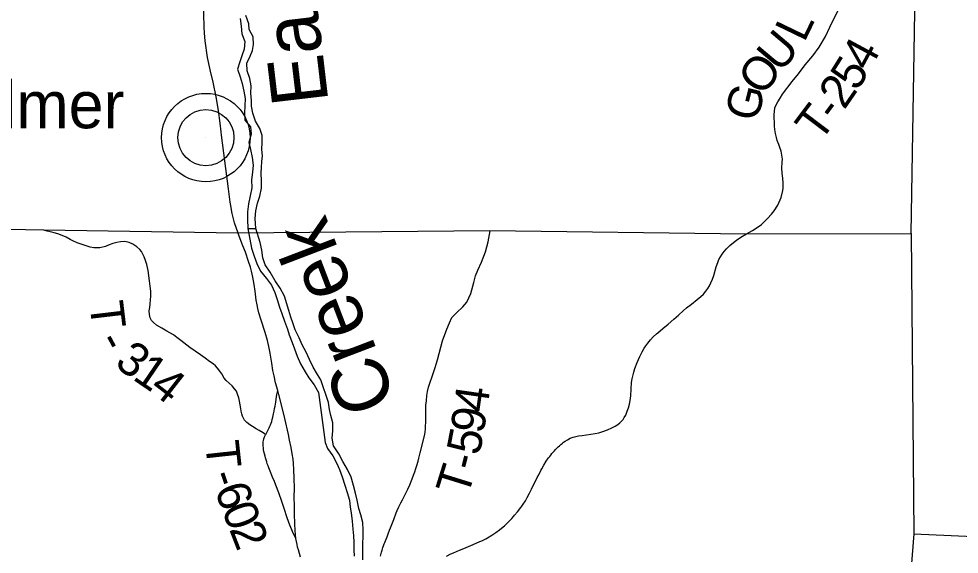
# Model space of a CAD drawing. Extents: x -10.5 to 40.6, y -3.2 to 22.
# Drawn here: x -7.693 to -6.111, y 16.857 to 17.758 of the extents above; entities that cross this region are included whole.
import ezdxf

# ---------------------------------------------------------------- set-up
doc = ezdxf.new("R2010")
doc.units = 0
for name, color, linetype in [('GM_X_Major_River', 7, 'Continuous'), ('GM_X_Major_River_Text', 7, 'Continuous'), ('GM_X_State_Route', 7, 'Continuous'), ('GM_X_Township_Road', 7, 'Continuous'), ('GM_X_Township_Road_Text', 7, 'Continuous'), ('GM_X_Township_Text', 7, 'Continuous'), ('GM_X_Unincorporated', 7, 'Continuous'), ('GM_X_Unincorporated_Location', 7, 'Continuous'), ('GM_X_Unincorporated_Text', 7, 'Continuous')]:
    doc.layers.add(name, color=color, linetype=linetype)

msp = doc.modelspace()

# ---------------------------------------------------------------- linework, layer by layer
at = {"layer": 'GM_X_Major_River'}
msp.add_line((-7.3076, 17.4047), (-7.2943, 17.4046), dxfattribs=at)
for points in [[(-7.2943, 17.4046), (-7.2951, 17.4214), (-7.2938, 17.4343), (-7.291, 17.4472), (-7.2875, 17.4594), (-7.2847, 17.4728), (-7.2846, 17.4853), (-7.2852, 17.4982), (-7.2843, 17.5077), (-7.2837, 17.5175), (-7.2827, 17.527), (-7.2841, 17.538), (-7.2832, 17.5494), (-7.2834, 17.5612), (-7.2874, 17.5732), (-7.2945, 17.5852), (-7.2993, 17.5988), (-7.3011, 17.6105), (-7.3013, 17.6204), (-7.3022, 17.6325), (-7.3017, 17.6446), (-7.3039, 17.6571), (-7.3087, 17.6703), (-7.3089, 17.6832), (-7.3038, 17.6946), (-7.2999, 17.7042), (-7.2982, 17.7141), (-7.2984, 17.727), (-7.3055, 17.7394), (-7.306, 17.7492), (-7.3109, 17.7632)], [(-7.3206, 17.758), (-7.3189, 17.7452), (-7.3178, 17.7323), (-7.3123, 17.7195), (-7.3139, 17.7066), (-7.3172, 17.697), (-7.3211, 17.6852), (-7.3247, 17.673), (-7.3202, 17.6602), (-7.317, 17.6489), (-7.3141, 17.636), (-7.3119, 17.6236), (-7.3125, 17.6114), (-7.3133, 17.5989), (-7.3127, 17.5871), (-7.303, 17.5756), (-7.302, 17.5635), (-7.3056, 17.5497), (-7.303, 17.5376), (-7.3001, 17.5244), (-7.2984, 17.5116), (-7.2996, 17.4994), (-7.3013, 17.4868), (-7.3007, 17.4732), (-7.3034, 17.4599), (-7.3062, 17.4462), (-7.3078, 17.4329), (-7.3083, 17.42), (-7.3076, 17.4047)], [(-7.3076, 17.4047), (-7.3013, 17.3718), (-7.2969, 17.3582), (-7.2926, 17.3457), (-7.2863, 17.3333), (-7.2759, 17.3205), (-7.2678, 17.3093), (-7.2623, 17.2972), (-7.258, 17.2855), (-7.254, 17.2727), (-7.2505, 17.2621), (-7.2458, 17.2492), (-7.2406, 17.2357), (-7.2379, 17.2258), (-7.2331, 17.213), (-7.2292, 17.2024), (-7.2245, 17.19), (-7.219, 17.1772), (-7.2109, 17.164), (-7.205, 17.1539), (-7.1961, 17.1418), (-7.1884, 17.129), (-7.1776, 17.0447)], [(-7.1845, 17.1501), (-7.1903, 17.1594), (-7.1977, 17.1718), (-7.2036, 17.1846), (-7.2094, 17.1966), (-7.216, 17.2091), (-7.2211, 17.2211), (-7.2281, 17.2343), (-7.2317, 17.246), (-7.2352, 17.2558), (-7.2384, 17.2668), (-7.2456, 17.291), (-7.2533, 17.3045), (-7.2615, 17.3169), (-7.27, 17.3312), (-7.2781, 17.3436), (-7.2825, 17.3553), (-7.2838, 17.3682), (-7.287, 17.3814), (-7.2943, 17.4046)], [(-7.1139, 16.8472), (-7.1141, 16.8726), (-7.1135, 16.8882), (-7.1136, 16.8981), (-7.1141, 16.9102), (-7.1172, 16.9231), (-7.1207, 16.9337), (-7.1239, 16.9477), (-7.1263, 16.9594), (-7.1298, 16.9727), (-7.1338, 16.9867), (-7.14, 16.9995), (-7.1477, 17.0131), (-7.1546, 17.026), (-7.1635, 17.0392), (-7.1659, 17.0521), (-7.1645, 17.0646), (-7.1646, 17.0779), (-7.1677, 17.09), (-7.1701, 17.1002), (-7.1721, 17.1124), (-7.1845, 17.1501)], [(-7.1776, 17.0447), (-7.1737, 17.0349), (-7.1645, 17.0225), (-7.1579, 17.0096), (-7.1536, 16.9994), (-7.1489, 16.9869), (-7.1446, 16.9733), (-7.1404, 16.9608), (-7.1364, 16.9479), (-7.1352, 16.9358), (-7.1336, 16.9263), (-7.1319, 16.9123), (-7.1307, 16.899), (-7.1298, 16.8876), (-7.1293, 16.8774), (-7.1292, 16.8641), (-7.1284, 16.8539)]]:
    msp.add_lwpolyline(points, dxfattribs=at)
at = {"layer": 'GM_X_State_Route'}
for points in [[(-7.3365, 17.4464), (-7.337, 17.4494), (-7.3399, 17.4715), (-7.3443, 17.5057), (-7.3519, 17.5616), (-7.3524, 17.5674), (-7.3541, 17.5819), (-7.3568, 17.6036), (-7.3605, 17.6264), (-7.3656, 17.6509), (-7.3703, 17.6696), (-7.3752, 17.6927), (-7.3794, 17.7205), (-7.3806, 17.7334), (-7.381, 17.7436), (-7.3823, 17.7886)], [(-7.3239, 17.3969), (-7.3298, 17.4143), (-7.3339, 17.4303), (-7.3365, 17.4464)], [(-7.2188, 16.8519), (-7.2207, 16.8583), (-7.2224, 16.8644), (-7.2237, 16.869), (-7.2247, 16.8735), (-7.2256, 16.8784), (-7.2265, 16.8831), (-7.2273, 16.8901), (-7.2279, 16.8969), (-7.2285, 16.908), (-7.2287, 16.9124), (-7.2289, 16.9204), (-7.229, 16.9272), (-7.2292, 16.9365), (-7.2292, 16.9427), (-7.2293, 16.9483), (-7.2294, 16.9526), (-7.2292, 16.9688), (-7.2294, 16.9843), (-7.2299, 16.9992), (-7.2307, 17.0097), (-7.2315, 17.017), (-7.2327, 17.0256), (-7.2347, 17.0366), (-7.2372, 17.0487), (-7.2392, 17.0584), (-7.2452, 17.0851), (-7.2503, 17.1062), (-7.2554, 17.1254), (-7.2573, 17.1324), (-7.2608, 17.1452), (-7.2634, 17.1568), (-7.2652, 17.1659), (-7.2672, 17.1782), (-7.2699, 17.1954), (-7.272, 17.2063), (-7.2745, 17.2166), (-7.2782, 17.2297), (-7.2852, 17.2509), (-7.2888, 17.2628), (-7.2906, 17.2701), (-7.2919, 17.2762), (-7.2932, 17.2842), (-7.2951, 17.2996), (-7.2968, 17.3107), (-7.2991, 17.3228), (-7.3013, 17.3331), (-7.3031, 17.3396), (-7.3063, 17.3496), (-7.3116, 17.3648), (-7.3158, 17.3757), (-7.3221, 17.3919), (-7.3239, 17.3969)]]:
    msp.add_lwpolyline(points, dxfattribs=at)
at = {"layer": 'GM_X_Township_Road'}
for points in [[(-6.469, 17.3956), (-6.4587, 17.4013), (-6.4491, 17.4075), (-6.4436, 17.4117), (-6.4385, 17.4166), (-6.4334, 17.4217), (-6.427, 17.429), (-6.4222, 17.4348), (-6.4161, 17.4439), (-6.4107, 17.4568), (-6.408, 17.4685), (-6.4075, 17.4726), (-6.4071, 17.4813), (-6.4078, 17.4893), (-6.4091, 17.4979), (-6.4094, 17.5064), (-6.409, 17.5164), (-6.4086, 17.5213), (-6.4094, 17.528), (-6.4107, 17.5349), (-6.4127, 17.5409), (-6.4148, 17.546), (-6.4172, 17.5526), (-6.4186, 17.558), (-6.42, 17.5644), (-6.421, 17.5711), (-6.4216, 17.5769), (-6.4221, 17.5829), (-6.4224, 17.5908), (-6.4225, 17.5964), (-6.422, 17.6018), (-6.421, 17.6076), (-6.4191, 17.6128), (-6.4164, 17.6181), (-6.4124, 17.6242), (-6.4082, 17.6308), (-6.3919, 17.6519), (-6.3817, 17.6653), (-6.37, 17.6804), (-6.3576, 17.6955), (-6.3469, 17.7101), (-6.3359, 17.7279), (-6.3285, 17.7433), (-6.3082, 17.7853)], [(-7.2772, 17.0584), (-7.2792, 17.0596), (-7.2815, 17.0609), (-7.2883, 17.0652), (-7.2933, 17.0681), (-7.2999, 17.0715), (-7.3041, 17.0744), (-7.3093, 17.0784), (-7.313, 17.0823), (-7.3164, 17.0889), (-7.3173, 17.0932), (-7.3187, 17.0977), (-7.3193, 17.1023), (-7.3215, 17.1145), (-7.3228, 17.12), (-7.3246, 17.1259), (-7.3268, 17.1313), (-7.3299, 17.1353), (-7.3337, 17.1404), (-7.3437, 17.1491), (-7.347, 17.1531), (-7.3511, 17.1602), (-7.3543, 17.1648), (-7.3583, 17.1701), (-7.3617, 17.1736), (-7.366, 17.1772), (-7.3718, 17.1813), (-7.3794, 17.1865), (-7.3873, 17.1924), (-7.3963, 17.1986), (-7.4049, 17.2048), (-7.4201, 17.2165), (-7.4271, 17.2213), (-7.4325, 17.226), (-7.4437, 17.2322), (-7.4523, 17.2371), (-7.4609, 17.2423), (-7.4662, 17.2469), (-7.4695, 17.25), (-7.4718, 17.2543), (-7.4729, 17.2604), (-7.4732, 17.2662), (-7.4722, 17.2718), (-7.4706, 17.291), (-7.4706, 17.2994), (-7.4717, 17.3078), (-7.4731, 17.3169), (-7.4753, 17.3341), (-7.4773, 17.3443), (-7.4793, 17.3511), (-7.4816, 17.357), (-7.4839, 17.3616), (-7.4862, 17.3659), (-7.4892, 17.3694), (-7.4944, 17.3741), (-7.5009, 17.3785), (-7.507, 17.3812), (-7.5143, 17.3828), (-7.5214, 17.3824), (-7.5276, 17.3813), (-7.5344, 17.3795), (-7.5407, 17.3774), (-7.5471, 17.3748), (-7.5562, 17.3726), (-7.5613, 17.3721), (-7.5667, 17.3724), (-7.5725, 17.3736), (-7.5796, 17.3759), (-7.5878, 17.3787), (-7.5943, 17.3808), (-7.6015, 17.3841), (-7.606, 17.3865), (-7.6131, 17.39), (-7.6198, 17.3931), (-7.6271, 17.3957), (-7.633, 17.3974), (-7.6399, 17.3992), (-7.6452, 17.4003), (-7.6507, 17.4021)], [(-7.0846, 16.8539), (-7.0827, 16.8604), (-7.0815, 16.8639), (-7.0802, 16.8681), (-7.0791, 16.8712), (-7.078, 16.8742), (-7.0769, 16.8769), (-7.0758, 16.8795), (-7.0748, 16.8822), (-7.0732, 16.8862), (-7.0713, 16.8914), (-7.0691, 16.8972), (-7.0675, 16.9012), (-7.062, 16.9156), (-7.0579, 16.9263), (-7.0561, 16.9307), (-7.0533, 16.9368), (-7.05, 16.9434), (-7.0476, 16.9484), (-7.0445, 16.9539), (-7.041, 16.9609), (-7.0384, 16.9664), (-7.0353, 16.9736), (-7.0312, 16.984), (-7.029, 16.9898), (-7.0268, 16.9956), (-7.0248, 17.001), (-7.0233, 17.006), (-7.021, 17.0133), (-7.0198, 17.0187), (-7.0174, 17.0272), (-7.0107, 17.0537), (-7.0098, 17.0591), (-7.0094, 17.0622), (-7.0089, 17.0677), (-7.0086, 17.0733), (-7.0084, 17.0782), (-7.0084, 17.0795), (-7.0084, 17.0819), (-7.0084, 17.0831), (-7.0083, 17.0861), (-7.0083, 17.0928), (-7.0082, 17.1002), (-7.0079, 17.1076), (-7.0073, 17.115), (-7.0064, 17.1237), (-7.0052, 17.1304), (-7.0035, 17.1377), (-7.002, 17.143), (-7.0009, 17.1466), (-6.9983, 17.1541), (-6.9959, 17.161), (-6.9924, 17.1712), (-6.9908, 17.1764), (-6.9887, 17.1841), (-6.9799, 17.2159), (-6.9731, 17.2356), (-6.9684, 17.2459), (-6.9644, 17.2549), (-6.9568, 17.2631), (-6.9462, 17.2728), (-6.9393, 17.281), (-6.9324, 17.2954), (-6.9277, 17.3141), (-6.9249, 17.3251), (-6.9208, 17.3347), (-6.9143, 17.3482), (-6.908, 17.3654), (-6.9033, 17.3826), (-6.9002, 17.401)], [(-6.9733, 16.8539), (-6.966, 16.8573), (-6.9615, 16.8593), (-6.9518, 16.8637), (-6.9444, 16.8668), (-6.9284, 16.8735), (-6.9175, 16.8782), (-6.9141, 16.8797), (-6.9108, 16.8813), (-6.9075, 16.883), (-6.9042, 16.8847), (-6.8972, 16.8887), (-6.8905, 16.8932), (-6.884, 16.8981), (-6.8779, 16.9032), (-6.876, 16.9049), (-6.871, 16.9095), (-6.8663, 16.9143), (-6.8637, 16.9169), (-6.8608, 16.9201), (-6.8588, 16.9225), (-6.854, 16.9282), (-6.8483, 16.9355), (-6.8465, 16.938), (-6.8443, 16.9411), (-6.8405, 16.9468), (-6.8375, 16.9524), (-6.8336, 16.9599), (-6.8302, 16.9666), (-6.8207, 16.9862), (-6.8184, 16.9906), (-6.8147, 16.9978), (-6.8133, 17.0005), (-6.8096, 17.0069), (-6.8056, 17.0132), (-6.8016, 17.0188), (-6.7997, 17.0212), (-6.798, 17.0238), (-6.7962, 17.0261), (-6.7937, 17.029), (-6.7919, 17.0311), (-6.79, 17.0331), (-6.7878, 17.0352), (-6.7857, 17.0374), (-6.7835, 17.0395), (-6.7812, 17.0416), (-6.7783, 17.044), (-6.7764, 17.0455), (-6.7739, 17.0473), (-6.7702, 17.0494), (-6.7652, 17.0519), (-6.7606, 17.0537), (-6.7558, 17.0551), (-6.7516, 17.056), (-6.7454, 17.0569), (-6.7306, 17.0587), (-6.7233, 17.0599), (-6.7172, 17.0613), (-6.7107, 17.0633), (-6.7025, 17.0664), (-6.6951, 17.0696), (-6.6896, 17.0725), (-6.6855, 17.0751), (-6.682, 17.0778), (-6.6789, 17.0808), (-6.6765, 17.0837), (-6.6744, 17.0867), (-6.6721, 17.0911), (-6.6694, 17.0974), (-6.6673, 17.1032), (-6.6657, 17.1092), (-6.6646, 17.1153), (-6.6636, 17.1233), (-6.6628, 17.1345), (-6.6621, 17.1456), (-6.6613, 17.1518), (-6.6603, 17.1567), (-6.6585, 17.1632), (-6.6566, 17.1691), (-6.6525, 17.1795), (-6.6481, 17.1897), (-6.6443, 17.1976), (-6.641, 17.2036), (-6.6383, 17.2077), (-6.6349, 17.2121), (-6.6305, 17.2174), (-6.6258, 17.2224), (-6.6205, 17.2276), (-6.6182, 17.2296), (-6.6096, 17.2368), (-6.6004, 17.2441), (-6.591, 17.2522), (-6.5832, 17.2593), (-6.575, 17.2669), (-6.5698, 17.2713), (-6.5614, 17.2778), (-6.5516, 17.2854), (-6.5459, 17.2902), (-6.5415, 17.2946), (-6.5374, 17.2992), (-6.5341, 17.3037), (-6.5312, 17.3085), (-6.5287, 17.3135), (-6.526, 17.3198), (-6.5241, 17.3257), (-6.5198, 17.3406), (-6.5173, 17.3476), (-6.5152, 17.3527), (-6.5128, 17.3571), (-6.5098, 17.3618), (-6.5064, 17.3663), (-6.5026, 17.3704), (-6.4968, 17.376), (-6.4907, 17.3813), (-6.4858, 17.3851), (-6.4786, 17.39), (-6.469, 17.3956)], [(-7.2772, 17.0584), (-7.2768, 17.0592), (-7.2715, 17.0697), (-7.2703, 17.0723), (-7.2693, 17.0748), (-7.2682, 17.0776), (-7.2674, 17.0801), (-7.2664, 17.0838), (-7.2655, 17.0873), (-7.2642, 17.0929), (-7.2632, 17.0975), (-7.2624, 17.1018), (-7.2616, 17.106), (-7.2606, 17.1125), (-7.2598, 17.1178), (-7.2585, 17.1255), (-7.2573, 17.1324)], [(-7.2265, 16.8831), (-7.2322, 16.8949), (-7.2335, 16.8977), (-7.2367, 16.9057), (-7.2411, 16.918), (-7.2464, 16.9338), (-7.2487, 16.9408), (-7.2514, 16.949), (-7.254, 16.9566), (-7.2552, 16.96), (-7.2603, 16.973), (-7.2629, 16.9793), (-7.2659, 16.9867), (-7.27, 16.9969), (-7.2722, 17.002), (-7.2735, 17.0055), (-7.2748, 17.0092), (-7.2757, 17.0125), (-7.2767, 17.0159), (-7.2775, 17.0188), (-7.2783, 17.0218), (-7.2795, 17.026), (-7.2804, 17.0297), (-7.281, 17.0326), (-7.2814, 17.0359), (-7.2817, 17.0395), (-7.2818, 17.0417), (-7.2817, 17.0441), (-7.2816, 17.0459), (-7.2812, 17.0483), (-7.2805, 17.0508), (-7.2793, 17.0542), (-7.2777, 17.0576), (-7.2772, 17.0584)]]:
    msp.add_lwpolyline(points, dxfattribs=at)
at = {"layer": 'GM_X_Township_Text'}
for points in [[(-6.192, 17.3965), (-6.1792, 18.1778), (-6.179, 18.1863), (-6.1678, 18.8746), (-6.1678, 18.8755), (-6.1618, 20.9), (-10.5445, 20.9), (-10.5445, 19.4241)], [(-10.5445, 19.4241), (-9.8621, 19.4152), (-9.3297, 19.4093), (-9.2736, 19.4089), (-9.2734, 18.9532), (-9.2666, 18.9242), (-9.2573, 18.7823), (-9.2552, 18.7211), (-9.2586, 18.705), (-9.2677, 18.6789), (-9.2756, 18.3974), (-9.1719, 18.3965), (-8.6421, 18.3977), (-8.2403, 18.3894), (-8.2411, 17.9704), (-8.2441, 17.4134), (-7.9861, 17.4086), (-7.6509, 17.4026), (-7.3241, 17.3974), (-6.9004, 17.4016), (-6.4692, 17.3961), (-6.192, 17.3965), (-6.1874, 16.891), (-6.062, 16.8858)], [(-6.1874, 16.891), (-6.1985, 16.7494), (-6.1956, 16.4198), (-6.1883, 16.2366), (-6.1993, 15.3843), (-6.2122, 14.1), (-3.7445, 14.1), (-3.7445, 16.8499)]]:
    msp.add_lwpolyline(points, dxfattribs=at)
at = {"layer": 'GM_X_Unincorporated'}
for radius in [0.0744, 0.0472]:
    msp.add_circle((-7.378, 17.5577), radius, dxfattribs=at)
at = {"layer": 'GM_X_Unincorporated_Location'}
msp.add_line((-7.378, 17.5577), (-7.378, 17.5577), dxfattribs=at)

# ---------------------------------------------------------------- texts
at = {"layer": 'GM_X_Major_River_Text'}
for s, rotation, p in [('East', 96.7272, (-7.1717, 17.6177)), ('Creek', 110.9056, (-7.057, 17.1136))]:
    msp.add_text(s, height=0.09469, rotation=rotation, dxfattribs=at).set_placement(p)
at = {"layer": 'GM_X_Township_Road_Text'}
for s, rotation, p in [('L', 64.2399, (-6.3718, 17.7165)), ('U', 49.8614, (-6.4125, 17.6652)), ('4', 61.68, (-6.2625, 17.6674)), ('O', 53.8368, (-6.4413, 17.6257)), ('5', 57.9623, (-6.2831, 17.6343)), ('2', 55.4314, (-6.3045, 17.6032)), ('G', 75.8242, (-6.4511, 17.5824)), ('T', 53.0264, (-6.3454, 17.5483)), ('-', 53.6513, (-6.3194, 17.5828)), ('T', 276.7827, (-7.574, 17.2796)), ('-', 298.3597, (-7.562, 17.2153)), ('3', 323.0882, (-7.5336, 17.1747)), ('1', 325.7708, (-7.5032, 17.152)), ('4', 322.031, (-7.4751, 17.1328)), ('4', 81.8922, (-6.9057, 17.0935)), ('9', 81.2838, (-6.9111, 17.0582)), ('5', 79.0728, (-6.9181, 17.0215)), ('T', 276.1921, (-7.3794, 17.045)), ('-', 75.7988, (-6.9246, 16.9954)), ('T', 72.7117, (-6.9381, 16.9516)), ('-', 288.6001, (-7.372, 16.9897)), ('6', 290.0661, (-7.364, 16.9661)), ('0', 290.4708, (-7.3519, 16.9328)), ('2', 291.1786, (-7.3393, 16.8993))]:
    msp.add_text(s, height=0.0568, rotation=rotation, dxfattribs=at).set_placement(p)
at = {"layer": 'GM_X_Unincorporated_Text'}
msp.add_text('Kilmer', height=0.07898, rotation=0, dxfattribs=at).set_placement((-7.8141, 17.5735))

doc.saveas('drawing.dxf')
